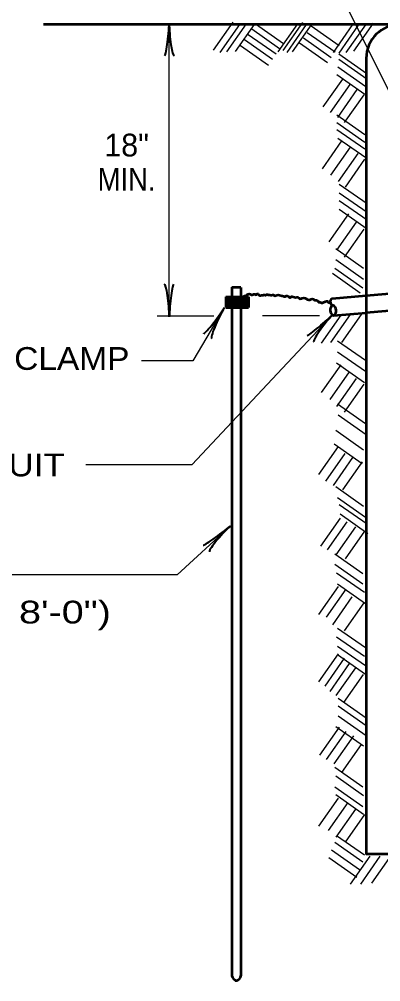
# Model space of a CAD drawing. Extents: x -1 to 679, y 0 to 440.
# Drawn here: x 300.7 to 332.7, y 43.4 to 128.7 of the extents above; entities that cross this region are included whole.
import ezdxf
from ezdxf.enums import TextEntityAlignment as Align

# ---------------------------------------------------------------- set-up
doc = ezdxf.new("R2010")
doc.units = 0
doc.header["$LTSCALE"] = 0.7
doc.linetypes.add('LONG_DASHED', pattern=[7.5, 6, -1.5])
doc.layers.add('1', color=7, linetype='Continuous', lineweight=53)

msp = doc.modelspace()

# ---------------------------------------------------------------- linework, layer by layer
at = {"layer": '1', "lineweight": 25}
for p, q in [((337.7117, 113.7762), (326.0517, 137.0762)), ((313.9717, 102.2963), (313.9717, 128.3162)), ((317.8918, 125.9363), (319.6318, 128.4162)), ((318.4717, 125.7362), (320.2117, 128.2163)), ((319.0718, 125.7762), (320.8117, 128.2562)), ((319.8317, 125.8162), (321.5718, 128.2962)), ((321.6117, 128.2763), (324.0917, 126.5362)), ((323.6117, 125.7762), (325.3517, 128.2562)), ((324.0718, 125.8962), (325.7917, 128.3762)), ((324.4117, 125.7362), (326.1318, 128.2163)), ((324.8918, 125.7762), (326.6318, 128.2562)), ((326.5317, 128.0962), (329.0118, 126.3563)), ((328.5317, 125.7362), (330.2518, 128.2163)), ((329.0118, 125.6762), (330.7518, 128.1562)), ((329.6517, 125.7163), (331.3918, 128.1762)), ((330.3317, 125.8563), (332.0718, 128.3363)), ((320.9717, 127.3362), (323.4518, 125.5962)), ((321.2717, 127.8162), (323.7518, 126.0962)), ((326.1918, 127.5162), (328.6717, 125.7963)), ((320.2917, 126.3563), (322.7717, 124.6162)), ((320.6318, 126.8762), (323.1117, 125.1362)), ((325.5118, 126.5763), (327.9917, 124.8362)), ((325.8517, 127.0362), (328.3317, 125.2963)), ((328.9917, 125.5962), (331.4717, 123.8563)), ((328.9917, 125.1362), (331.4717, 123.3962)), ((328.8317, 123.7762), (331.3117, 122.0362)), ((328.9117, 124.4562), (331.3918, 122.7163)), ((327.6117, 120.9162), (329.3517, 123.3762)), ((328.2518, 120.4162), (329.9917, 122.8962)), ((328.9117, 119.9562), (330.6318, 122.4363)), ((329.5118, 119.5162), (331.2518, 121.9762)), ((328.8317, 120.1962), (331.3117, 118.4562)), ((328.8317, 119.5162), (331.3117, 117.7762)), ((328.8317, 118.8962), (331.3117, 117.1762)), ((327.5517, 115.4162), (329.2717, 117.8962)), ((328.9117, 118.1362), (331.3918, 116.4162)), ((328.2917, 114.8563), (330.0317, 117.3362)), ((328.9717, 114.2963), (330.7117, 116.7762)), ((329.5917, 113.7963), (331.3117, 116.2762)), ((329.0317, 114.0562), (331.5118, 112.3362)), ((329.0317, 113.2963), (331.5118, 111.5763)), ((329.0317, 112.6162), (331.5118, 110.8962)), ((329.0317, 111.8362), (331.5118, 110.0962)), ((328.1517, 108.9562), (329.8918, 111.4363)), ((328.8317, 108.1962), (330.5718, 110.6762)), ((329.5118, 107.5962), (331.2518, 110.0763)), ((328.7317, 108.3563), (331.1918, 106.6162)), ((328.7317, 107.3762), (331.1918, 105.6362)), ((328.4317, 106.1562), (330.8918, 104.4162)), ((328.6517, 106.6162), (331.1318, 104.8762)), ((322.2317, 102.4162), (327.2717, 102.4162)), ((327.4717, 99.9562), (329.1918, 102.4363)), ((328.2917, 100.0362), (330.0317, 102.5162)), ((329.2717, 100.0362), (331.0118, 102.5162)), ((312.8918, 102.3762), (317.9317, 102.3762)), ((328.8717, 100.1762), (331.3517, 98.4562)), ((328.8717, 99.1962), (331.3517, 97.4762)), ((328.7917, 98.2163), (331.2717, 96.4762)), ((327.4717, 95.5763), (329.1918, 98.0562)), ((328.2317, 94.9762), (329.9518, 97.4363)), ((328.8317, 94.3563), (330.5718, 96.8362)), ((329.5118, 93.8362), (331.2518, 96.3162)), ((328.8717, 94.5962), (331.3517, 92.8563)), ((328.9518, 93.5962), (331.4317, 91.8762)), ((328.7317, 92.2362), (331.1918, 90.5162)), ((327.2317, 88.3162), (328.9717, 90.7963)), ((328.5718, 91.0362), (331.0517, 89.2963)), ((327.8517, 87.7163), (329.5718, 90.1762)), ((328.5317, 87.3362), (330.2518, 89.8162)), ((329.3517, 86.9562), (331.0917, 89.4363)), ((328.7317, 87.2562), (331.1918, 85.5162)), ((328.8717, 86.2762), (331.3517, 84.5362)), ((329.0317, 85.6562), (331.5118, 83.9363)), ((329.1117, 84.8362), (331.5718, 83.0962)), ((327.3918, 81.9562), (329.1318, 84.4363)), ((327.9917, 81.6562), (329.7317, 84.1363)), ((328.7518, 81.1962), (330.4917, 83.6762)), ((329.5917, 80.8362), (331.3117, 83.2963)), ((328.6517, 81.2762), (331.1318, 79.5362)), ((328.6517, 80.3762), (331.1318, 78.6363)), ((328.7917, 79.6162), (331.2717, 77.8762)), ((328.8717, 78.6363), (331.3517, 76.8962)), ((327.2317, 75.9162), (328.9717, 78.3962)), ((327.9117, 75.6762), (329.6517, 78.1562)), ((328.4518, 74.9963), (330.1918, 77.4762)), ((329.5118, 74.4762), (331.2518, 76.9562)), ((328.8717, 74.6962), (331.3517, 72.9762)), ((328.7917, 73.9363), (331.2717, 72.2163)), ((328.8717, 73.1162), (331.3517, 71.3762)), ((327.2317, 69.9363), (328.9717, 72.4162)), ((327.7717, 69.5562), (329.5118, 72.0362)), ((328.8717, 72.3563), (331.3517, 70.6162)), ((328.2317, 69.0962), (329.9518, 71.5763)), ((328.7518, 68.7362), (330.4917, 71.1962)), ((329.4317, 68.1162), (331.1717, 70.5962)), ((328.9518, 68.4963), (331.4317, 66.7562)), ((328.9518, 67.8162), (331.4317, 66.0763)), ((328.9518, 66.9162), (331.4317, 65.1762)), ((327.3117, 63.4363), (329.0517, 65.9162)), ((328.7317, 65.9963), (331.1918, 64.2763)), ((327.9117, 63.0562), (329.6517, 65.5362)), ((328.5917, 62.6762), (330.3317, 65.1562)), ((329.2717, 61.9162), (331.0118, 64.3962)), ((328.6517, 62.3762), (331.1318, 60.6362)), ((328.7317, 61.6163), (331.1918, 59.8762)), ((328.6517, 60.6362), (331.1318, 58.8962)), ((328.7317, 59.9562), (331.1918, 58.2162)), ((327.2317, 57.1562), (328.9717, 59.6362)), ((328.0718, 56.7762), (329.8117, 59.2563)), ((328.7518, 56.1762), (330.4917, 58.6562)), ((329.5917, 55.7162), (331.3117, 58.1962)), ((328.7917, 56.3162), (331.2717, 54.5962)), ((328.6517, 55.7162), (331.1318, 53.9763)), ((328.3517, 55.0362), (330.8317, 53.2963)), ((328.1117, 54.3562), (330.5917, 52.6163)), ((330.0317, 52.0162), (331.7717, 54.4962)), ((330.9518, 52.0162), (332.6717, 54.4962)), ((331.9317, 52.0962), (333.6717, 54.5763))]:
    msp.add_line(p, q, dxfattribs=at)
at = {"layer": '1'}
for p, q in [((302.8317, 128.2362), (337.2117, 128.2362)), ((319.5118, 104.9162), (320.3117, 104.9162)), ((319.5118, 104.9162), (319.5118, 104.1362)), ((319.5118, 104.1762), (319.5118, 101.8162)), ((320.3117, 104.8962), (320.3117, 104.5763)), ((320.3117, 104.8962), (320.3117, 104.1362)), ((320.3117, 104.1762), (320.3117, 101.8563)), ((328.3918, 103.9162), (331.4117, 104.1762)), ((318.9917, 104.0562), (320.9917, 104.0562)), ((318.9917, 104.0562), (318.9917, 103.1362)), ((319.0317, 104.0562), (319.0317, 103.1362)), ((319.0317, 104.0562), (319.0317, 103.1362)), ((319.0517, 104.0562), (319.0517, 103.1362)), ((319.0718, 104.0562), (319.0718, 103.1362)), ((319.0917, 104.0562), (319.0917, 103.1362)), ((319.1517, 104.0562), (319.1517, 103.1362)), ((319.1918, 104.0562), (319.1918, 103.1362)), ((319.2317, 104.0562), (319.2317, 103.1362)), ((319.2518, 104.0562), (319.2518, 103.1362)), ((319.2917, 104.0562), (319.2917, 103.1362)), ((319.3118, 104.0562), (319.3118, 103.1362)), ((319.3317, 104.0562), (319.3317, 103.1362)), ((319.3717, 104.0562), (319.3717, 103.1362)), ((319.3717, 104.0562), (319.3717, 103.1362)), ((319.3717, 104.0562), (319.3717, 103.1362)), ((319.3918, 104.0562), (319.3918, 103.1362)), ((319.4117, 104.0562), (319.4117, 103.1362)), ((319.4317, 104.0562), (319.4317, 103.1362)), ((319.4317, 104.0562), (319.4317, 103.1362)), ((319.4717, 104.0562), (319.4717, 103.1362)), ((319.4717, 104.0562), (319.4717, 103.1362)), ((319.4717, 104.0562), (319.4717, 103.1362)), ((319.5118, 104.0562), (319.5118, 103.1362)), ((319.5317, 104.0562), (319.5317, 103.1362)), ((319.5317, 104.0562), (319.5317, 103.1362)), ((319.5718, 104.0562), (319.5718, 103.1362)), ((319.5718, 104.0562), (319.5718, 103.1362)), ((319.5917, 104.0562), (319.5917, 103.1362)), ((319.5917, 104.0562), (319.5917, 103.6962)), ((319.6318, 104.0562), (319.6318, 103.1362)), ((319.6318, 104.0562), (319.6318, 103.1362)), ((319.6517, 104.0562), (319.6517, 103.1362)), ((319.6717, 104.0562), (319.6717, 103.1362)), ((319.6918, 104.0562), (319.6918, 103.1362)), ((319.7317, 104.0562), (319.7317, 103.1362)), ((319.7317, 104.0562), (319.7317, 103.1362)), ((319.7717, 104.0562), (319.7717, 103.1362)), ((319.7917, 104.0562), (319.7917, 103.1362)), ((319.8118, 104.0562), (319.8118, 103.1362)), ((319.8118, 104.0562), (319.8118, 103.1362)), ((319.8317, 104.0562), (319.8317, 103.1362)), ((319.8517, 104.0562), (319.8517, 103.1362)), ((319.8717, 104.0562), (319.8717, 103.1362)), ((319.8918, 104.0562), (319.8918, 103.1362)), ((319.8918, 104.0562), (319.8918, 103.1362)), ((319.8918, 104.0562), (319.8918, 103.1362)), ((319.9117, 104.0562), (319.9117, 103.1362)), ((319.9117, 104.0562), (319.9117, 103.1362)), ((319.9117, 104.0562), (319.9117, 103.1362)), ((319.9518, 104.0562), (319.9518, 103.1362)), ((319.9518, 104.0562), (319.9518, 103.1362)), ((319.9717, 104.0562), (319.9717, 103.1362)), ((319.9717, 104.0562), (319.9717, 103.1362)), ((319.9917, 104.0562), (319.9917, 103.1362)), ((320.0118, 104.0562), (320.0118, 103.1362)), ((320.0517, 104.0562), (320.0517, 103.1362)), ((320.0517, 104.0562), (320.0517, 103.1362)), ((320.0517, 104.0562), (320.0517, 103.1362)), ((320.0718, 104.0562), (320.0718, 103.1362)), ((320.0917, 104.0562), (320.0917, 103.1362)), ((320.1117, 104.0562), (320.1117, 103.1362)), ((320.1117, 104.0562), (320.1117, 103.1362)), ((320.1318, 104.0562), (320.1318, 103.1362)), ((320.1318, 104.0562), (320.1318, 103.1362)), ((320.1717, 104.0562), (320.1717, 103.1362)), ((320.1918, 104.0562), (320.1918, 103.1362)), ((320.1918, 104.0562), (320.1918, 103.1362)), ((320.2117, 104.0562), (320.2117, 103.1362)), ((320.2518, 104.0562), (320.2518, 103.1362)), ((320.2518, 104.0562), (320.2518, 103.1362)), ((320.2518, 104.0562), (320.2518, 103.1362)), ((320.2717, 104.0562), (320.2717, 103.1362)), ((320.2717, 104.0562), (320.2717, 103.1362)), ((320.2917, 104.0562), (320.2917, 103.1362)), ((320.2917, 104.0562), (320.2917, 103.1362)), ((320.3117, 104.0562), (320.3117, 103.1362)), ((320.3317, 104.0562), (320.3317, 103.1362)), ((320.3317, 104.0562), (320.3317, 103.1362)), ((320.3317, 104.0562), (320.3317, 103.1362)), ((320.3517, 104.0562), (320.3517, 103.1362)), ((320.3717, 104.0562), (320.3717, 103.1362)), ((320.3918, 104.0562), (320.3918, 103.1362)), ((320.3918, 104.0562), (320.3918, 103.6962)), ((320.4117, 104.0562), (320.4117, 103.1362)), ((320.4117, 104.0562), (320.4117, 103.1362)), ((320.4117, 104.0562), (320.4117, 103.1362)), ((320.4518, 104.0562), (320.4518, 103.1362)), ((320.4717, 104.0562), (320.4717, 103.1362)), ((320.4917, 104.0562), (320.4917, 103.1362)), ((320.4917, 104.0562), (320.4917, 103.1362)), ((320.5118, 104.0562), (320.5118, 103.1362)), ((320.5317, 104.0562), (320.5317, 103.1362)), ((320.5317, 104.0562), (320.5317, 103.1362)), ((320.5718, 104.0562), (320.5718, 103.1362)), ((320.5917, 104.0562), (320.5917, 103.1362)), ((320.6117, 104.0562), (320.6117, 103.1362)), ((320.6117, 104.0562), (320.6117, 103.1362)), ((320.6117, 104.0562), (320.6117, 103.1362)), ((320.6117, 104.0562), (320.6117, 103.1362)), ((320.6517, 104.0562), (320.6517, 103.1362)), ((320.6517, 104.0562), (320.6517, 103.1362)), ((320.6517, 104.0562), (320.6517, 103.1362)), ((320.6717, 104.0562), (320.6717, 103.1362)), ((320.6918, 104.0562), (320.6918, 103.1362)), ((320.6918, 104.0562), (320.6918, 103.1362)), ((320.7117, 104.0562), (320.7117, 103.1362)), ((320.7317, 104.0562), (320.7317, 103.1362)), ((320.7518, 104.0562), (320.7518, 103.1362)), ((320.7518, 104.0562), (320.7518, 103.1362)), ((320.7518, 104.0562), (320.7518, 103.1362)), ((320.7518, 104.0562), (320.7518, 103.1362)), ((320.7917, 104.0562), (320.7917, 103.1362)), ((320.8117, 104.0562), (320.8117, 103.1362)), ((320.8117, 104.0562), (320.8117, 103.1362)), ((320.8117, 104.0562), (320.8117, 103.1362)), ((320.8117, 104.0562), (320.8117, 103.1362)), ((320.8517, 104.0562), (320.8517, 103.1362)), ((320.8517, 104.0562), (320.8517, 103.1362)), ((320.8517, 104.0562), (320.8517, 103.1362)), ((320.8717, 104.0562), (320.8717, 103.1362)), ((320.8717, 104.0562), (320.8717, 103.1362)), ((320.8717, 104.0562), (320.8717, 103.1362)), ((320.8918, 104.0562), (320.8918, 103.1362)), ((320.8918, 104.0562), (320.8918, 103.1362)), ((320.9317, 104.0562), (320.9317, 103.1362)), ((320.9317, 104.0562), (320.9317, 103.1362)), ((320.9317, 104.0562), (320.9317, 103.1362)), ((320.9518, 104.0562), (320.9518, 103.1362)), ((320.9518, 104.0562), (320.9518, 103.1362)), ((320.9717, 104.0562), (320.9717, 103.1362)), ((320.9717, 104.0562), (320.9717, 103.1362)), ((320.9917, 104.0562), (320.9917, 103.1362)), ((320.9917, 104.0562), (320.9917, 103.1362)), ((318.9917, 103.1362), (320.9917, 103.1362)), ((328.5317, 102.4162), (331.4317, 102.6562)), ((319.5118, 102.0562), (319.5118, 43.8762)), ((320.3117, 102.0562), (320.3117, 43.8762)), ((319.9117, 43.4562), (319.9117, 43.3562))]:
    msp.add_line(p, q, dxfattribs=at)
at = {"layer": '1', "linetype": 'LONG_DASHED'}
for p, q in [((331.4317, 104.1962), (341.5917, 105.0763)), ((331.4317, 102.6762), (342.1918, 103.6162))]:
    msp.add_line(p, q, dxfattribs=at)
at = {"layer": '1'}
msp.add_lwpolyline([(331.4317, 125.2163), (331.4317, 54.6962), (368.9317, 54.6962)], dxfattribs=at)
at = {"layer": '1', "lineweight": 25}
for points in [[(328.4518, 102.4963), (315.9717, 89.1762), (306.5718, 89.1762)], [(318.8317, 103.0962), (316.0517, 98.3962), (311.4917, 98.3962)], [(319.3717, 83.7362), (314.6717, 79.4162), (294.1517, 79.4162)]]:
    msp.add_lwpolyline(points, dxfattribs=at)
at = {"layer": '1'}
for centre, radius, start, end in [((334.4522, 125.2117), 3.024, 90, 180), ((328.7636, 102.8943), 0.5346, 124.39884, 244.42408), ((320.0634, 43.9933), 0.5596, 191.11811, 254.886), ((319.772, 43.9933), 0.5596, 285.114, 348.88189)]:
    msp.add_arc(centre, radius, start, end, dxfattribs=at)
at = {"layer": '1', "lineweight": 25}
msp.add_arc((334.4522, 125.2117), 3.024, 90, 180, dxfattribs=at)
at = {"layer": '1', "lineweight": 40}
for centre, major_axis, ratio, start_param, end_param in [((313.7506, 127.1934), (0.1771, 1.7705), 0.07063, 3.1407148, 5.41811), ((314.2424, 127.2229), (-0.1574, 1.8), 0.122415, 0.8963533, 3.1415927), ((313.6854, 103.4042), (0.1574, -1.8), 0.122415, 0.8963533, 3.1415927), ((314.1772, 103.4337), (0.1771, 1.7705), 0.07063, 6.2823074, 8.5597026), ((318.0784, 102.2333), (1.0593, 1.4296), 0.07063, 3.1407148, 5.41811), ((318.5158, 102.0066), (0.7873, 1.6263), 0.122415, 0.8963533, 3.1415927), ((327.5161, 101.8108), (-1.3401, -1.1705), 0.07063, 6.2823074, 8.5597026), ((327.8951, 101.496), (1.1163, 1.4208), 0.122415, 0.8963533, 3.1415927), ((318.3939, 83.1275), (-1.4232, -1.0679), 0.07063, 6.2823074, 8.5597026), ((318.7485, 82.7855), (1.2185, 1.3341), 0.122415, 0.8963533, 3.1415927)]:
    msp.add_ellipse(centre, major_axis=major_axis, ratio=ratio, start_param=start_param, end_param=end_param, dxfattribs=at)
at = {"layer": '1'}
for centre, major_axis, ratio, start_param, end_param in [((328.5681, 103.6536), (-0.2991, -0.1888), 0.884789, 4.712389, 7.0289039), ((328.2317, 102.8535), (-0.4869, 0.2208), 0.984898, 2.6109211, 4.7123118)]:
    msp.add_ellipse(centre, major_axis=major_axis, ratio=ratio, start_param=start_param, end_param=end_param, dxfattribs=at)
msp.add_spline([(320.4717, 104.0562), (320.7518, 104.1962), (321.1517, 104.3162), (321.2518, 104.2362), (321.5517, 104.3162), (321.6717, 104.2562), (321.7917, 104.3362), (321.9917, 104.1962), (322.1318, 104.2163), (322.2917, 104.2163), (322.4317, 104.2362), (322.4917, 104.2163), (322.6318, 104.2963), (322.6918, 104.2562), (322.8918, 104.2362), (323.0317, 104.2163), (323.2117, 104.2362), (323.2717, 104.1762), (323.4117, 104.1962), (323.6117, 104.2362), (323.8517, 104.1962), (323.9317, 104.1562), (324.0917, 104.1362), (324.1918, 104.0962), (324.4317, 104.1562), (324.6918, 104.0162), (324.7917, 104.0962), (325.1517, 104.0162), (325.3717, 104.0362), (325.5118, 103.9162), (325.7518, 103.9562), (326.0118, 103.9562), (326.2317, 103.8362), (326.4317, 103.8162), (326.5317, 103.8563), (326.7518, 103.8563), (326.8517, 103.7762), (326.9317, 103.7762), (327.1717, 103.6562), (327.2317, 103.5763), (327.2317, 103.5962), (327.4717, 103.5362), (327.6117, 103.5763), (327.8918, 103.6762), (328.0118, 103.6562), (328.0517, 103.5962), (328.0917, 103.5562), (328.1517, 103.5562), (328.3317, 103.5162)], degree=3, dxfattribs=at)

# ---------------------------------------------------------------- texts
msp.add_text('18"', height=2.016, dxfattribs=at).set_placement((310.1879, 116.5162), align=Align.CENTER)
at = {"layer": '1', "width": 0.9}
msp.add_text('MIN.', height=2.016, dxfattribs=at).set_placement((310.1805, 113.4762), align=Align.CENTER)
at = {"layer": '1'}
for s, width, p in [('GROUND WIRE CLAMP', 1.1, (277.6517, 97.5962)), ('1/2" CONDUIT', 1.15, (284.3118, 88.1562)), ('GROUND ROD (3/4" X 8\'-0")', 1.3, (263.7717, 75.1162))]:
    msp.add_text(s, height=2.016, dxfattribs=dict(at, width=width)).set_placement(p)

doc.saveas('drawing.dxf')
